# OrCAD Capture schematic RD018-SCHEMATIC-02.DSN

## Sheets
1 2: size A3
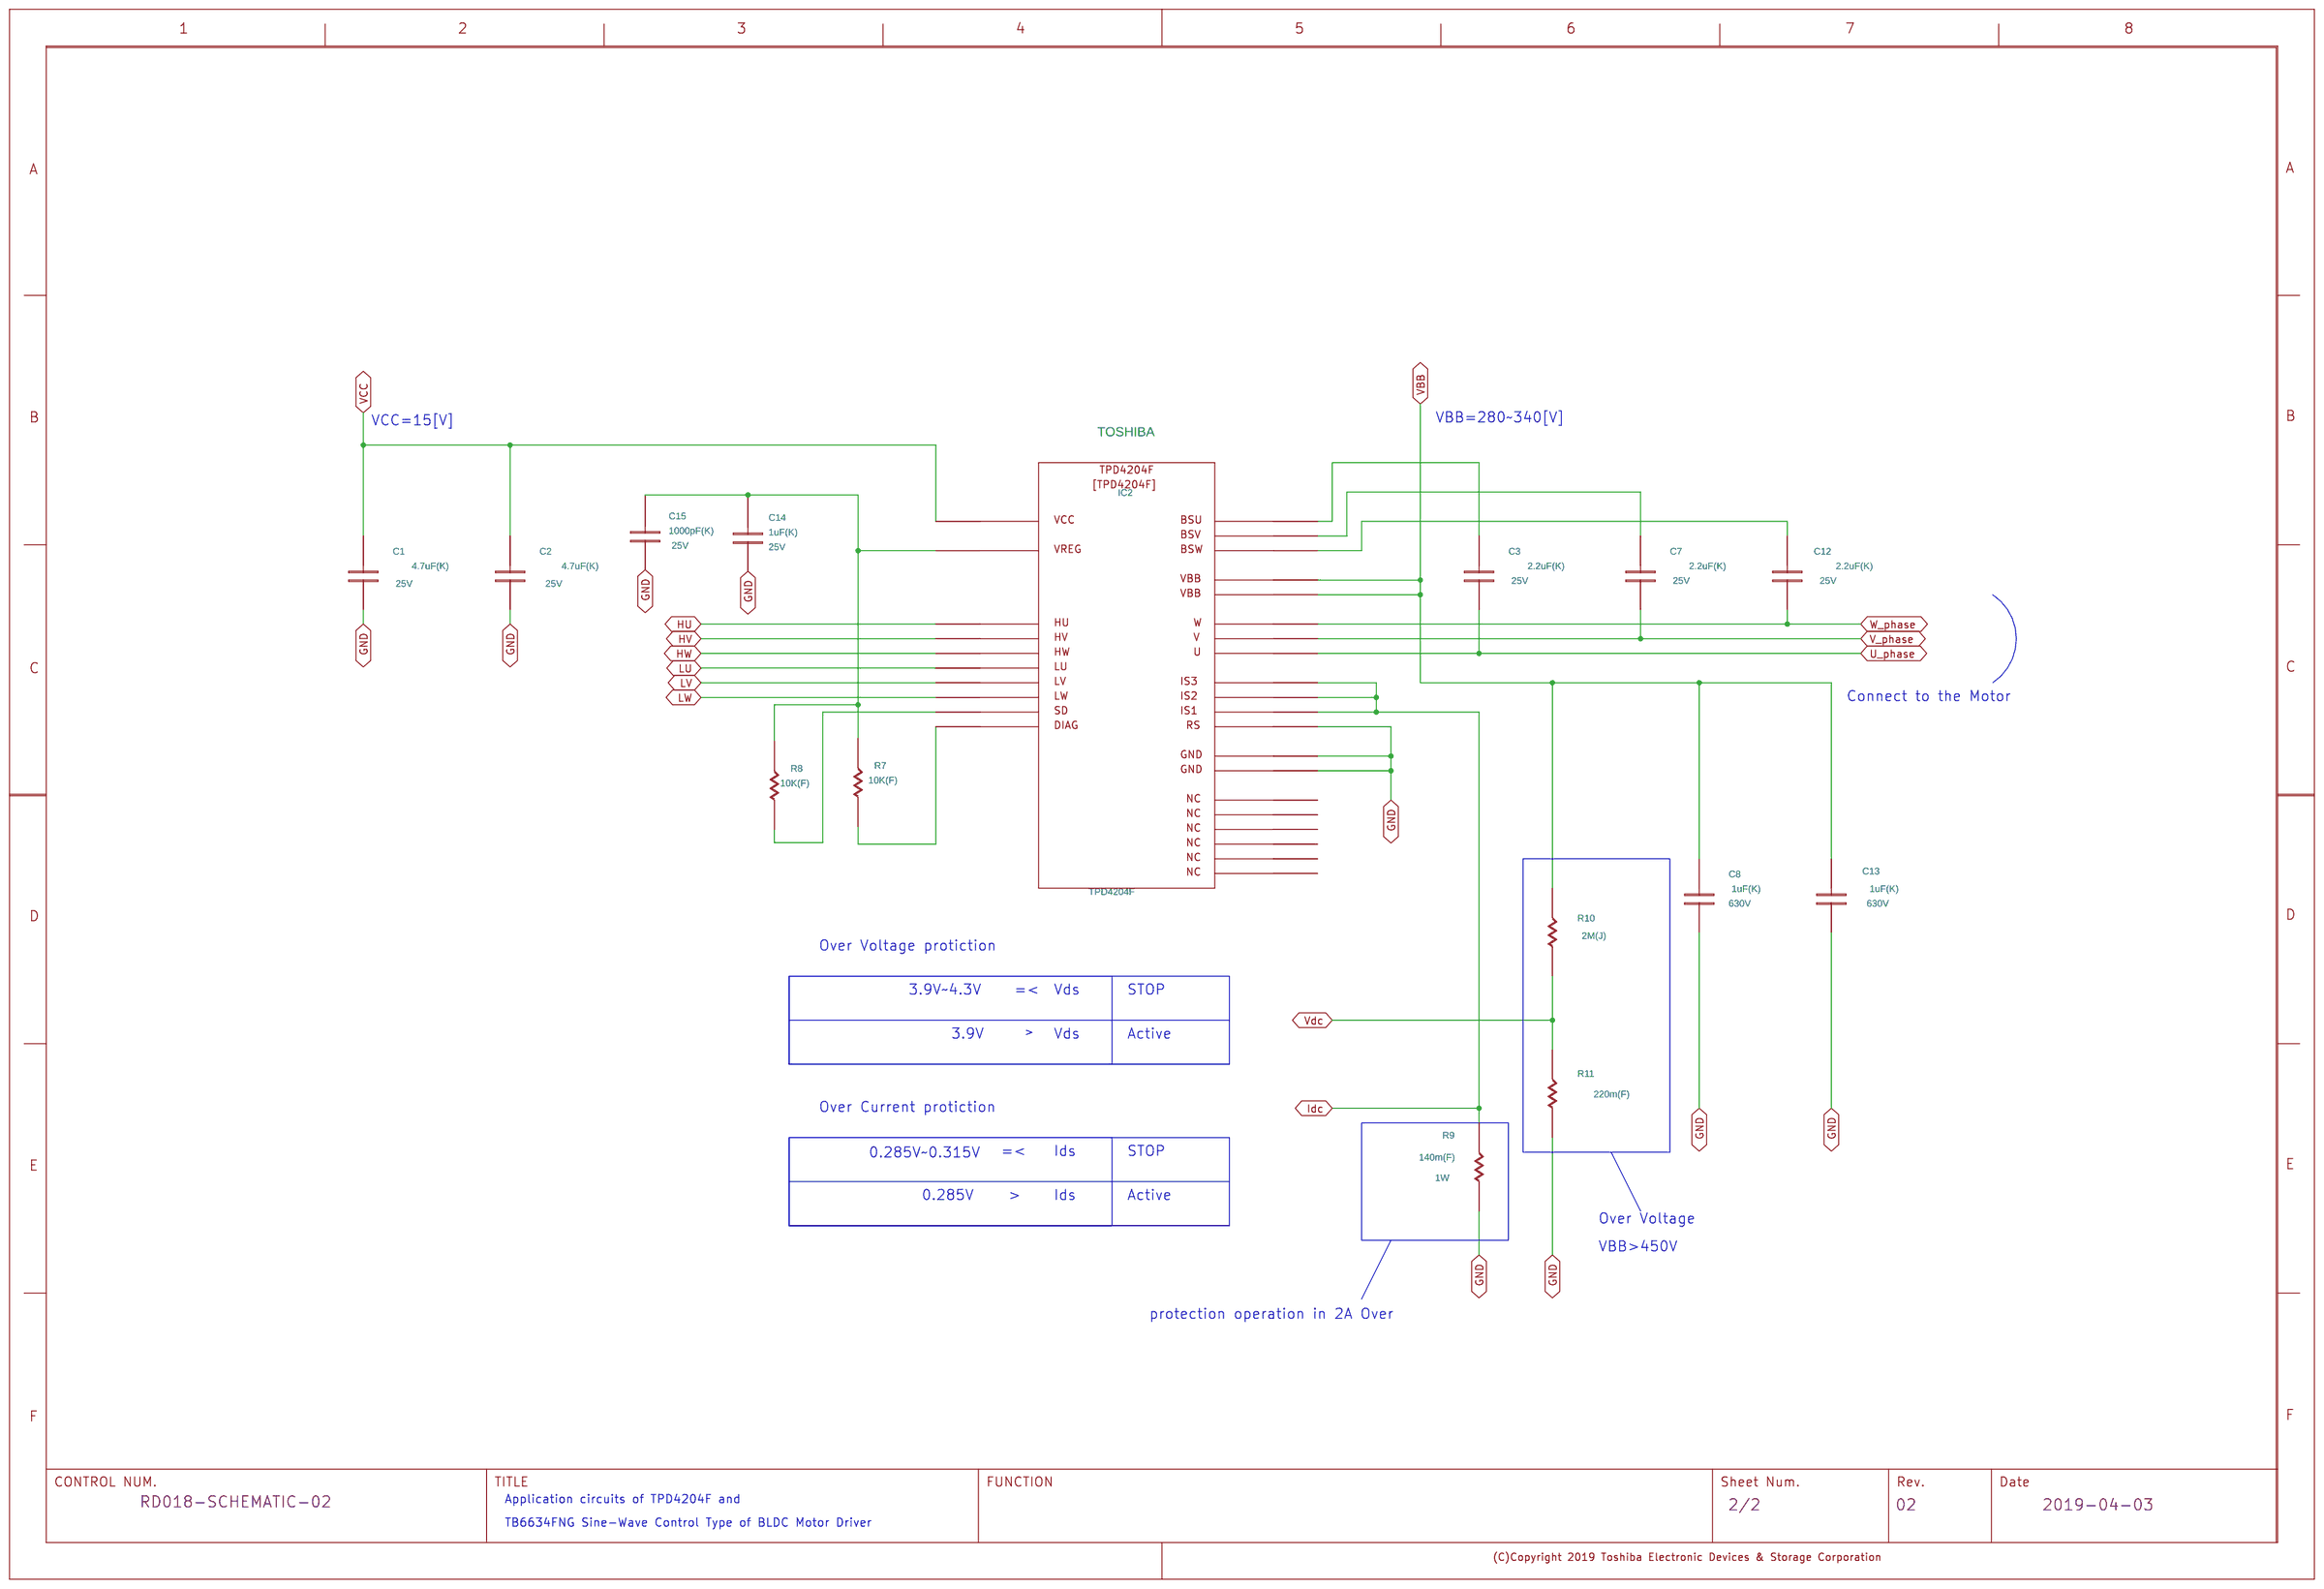
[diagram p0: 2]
2 1: size A3
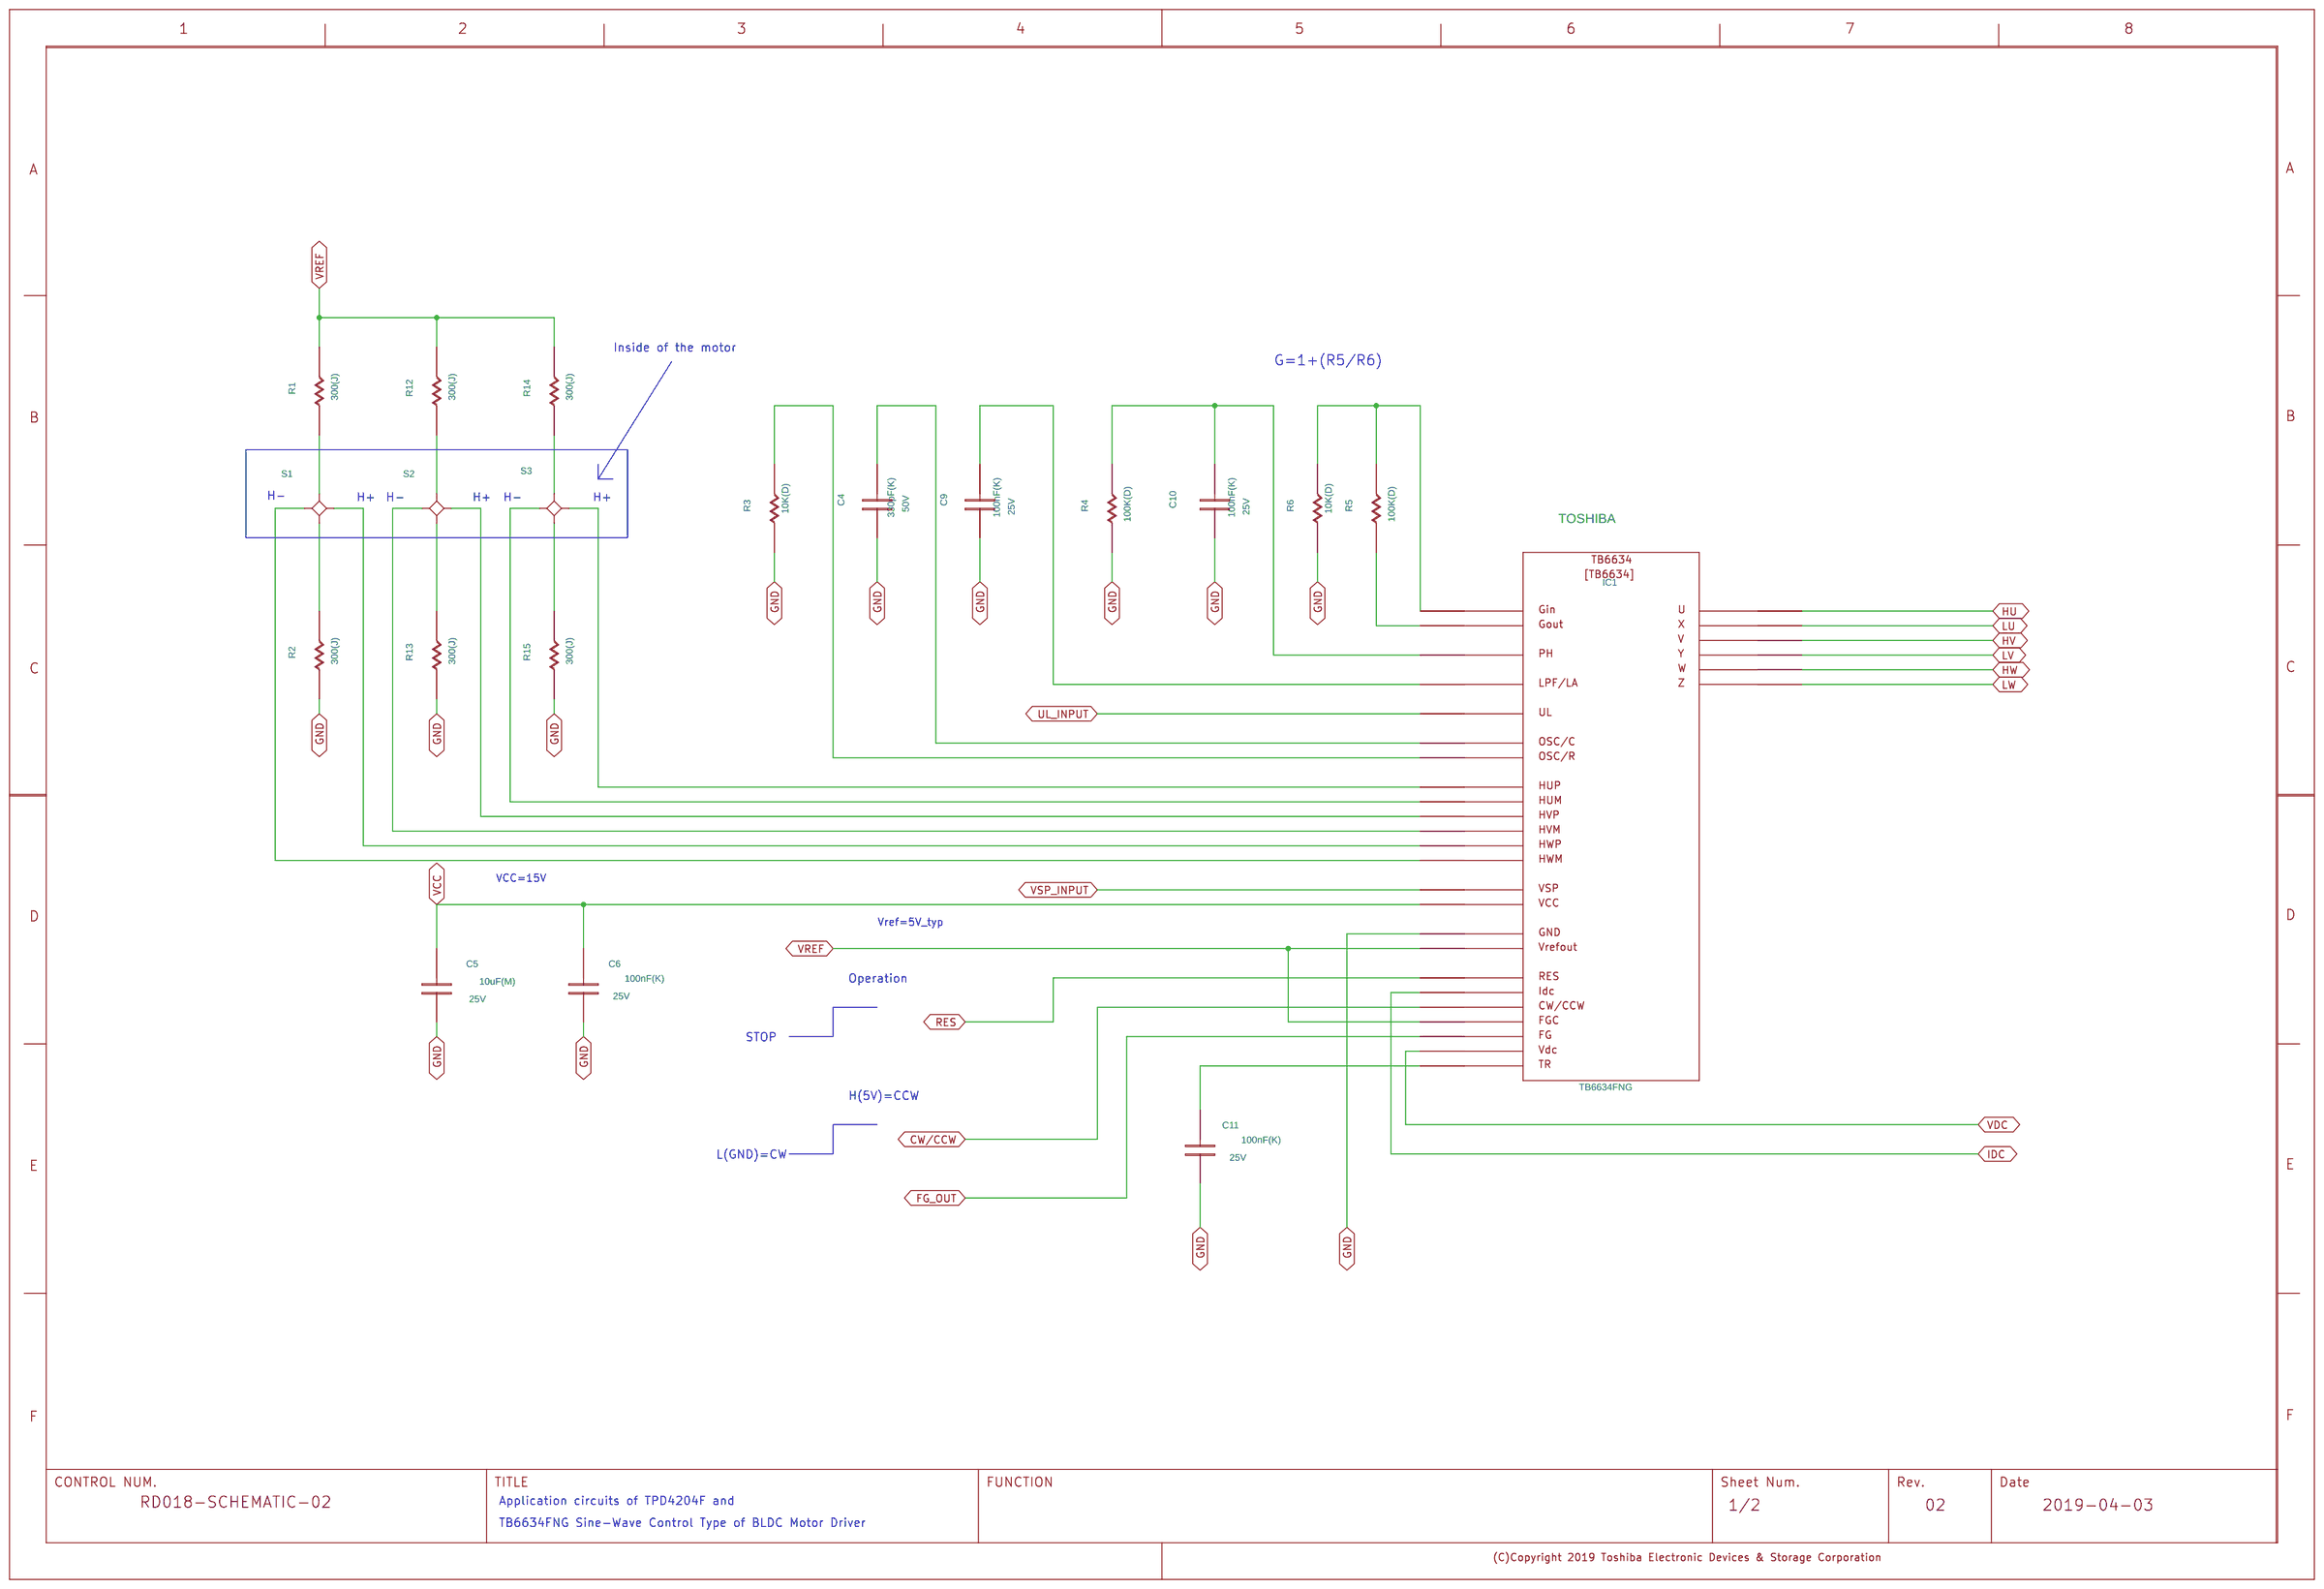
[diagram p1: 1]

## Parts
sheet 1
C4  C
C5  C
C6  C
C9  C
C10  C
C11  C
IC1  S-TB6634
R1  R
R2  R
R3  R
R4  R
R5  R
R6  R
R12  R
R13  R
R14  R
R15  R
S1  STAR4
S2  STAR4
S3  STAR4
U?#1  WAKU_DEF100
sheet 2
C1  C
C2  C
C3  C
C7  C
C8  C
C12  C
C13  C
C14  C
C15  C
IC2  S-TPD4204F
R7  R
R8  R
R9  R
R10  R
R11  R
U?#2  WAKU_DEF100

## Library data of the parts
C4 = C: COMPONENTTYPE: 4; GCOUNT: 1; MAXGCOUNT: 1; SIZECODESMD: 1608; VAL1: 330pF(K); VAL2: 50V
C5 = C: COMPONENTTYPE: 4; GCOUNT: 1; MAXGCOUNT: 1; SIZECODESMD: 2012; VAL1: 10uF(M); VAL2: 25V
C6 C9-C11 = C: COMPONENTTYPE: 4; GCOUNT: 1; MAXGCOUNT: 1; SIZECODESMD: 1608; VAL1: 100nF(K); VAL2: 25V
IC1 = S-TB6634: COMPONENTTYPE: 4; OUMEPARTTYPE: IC; SIZECODESMD: SSOP30; USERCOMPTEXT1: TB6634FNG; USERCOMPTEXT3: TOSHIBA; VAL1: TB6634FNG; VAL3: TB6634FNG
R1 R2 R12-R15 = R: COMPONENTTYPE: 4; GCOUNT: 1; MAXGCOUNT: 1; SIZECODESMD: 1608; VAL1: 300(J); VAL2: 100mW
R3 R6 = R: COMPONENTTYPE: 4; GCOUNT: 1; MAXGCOUNT: 1; SIZECODESMD: 1608; VAL1: 10K(D); VAL2: 100mW
R4 R5 = R: COMPONENTTYPE: 4; GCOUNT: 1; MAXGCOUNT: 1; SIZECODESMD: 1608; VAL1: 100K(D); VAL2: 100mW
S1-S3 = STAR4: COMPONENTTYPE: 4; OUMEPARTTYPE: IC; SIZECODESMD: 4SOP; VAL1: HW-101A; VAL3: HW-101A
U?#1 = WAKU_DEF100: COMPONENTTYPE: 2; DATE: 2019-04-03; DRAWINGNUMBER: RD018-SCHEMATIC-02; REVISION: 02; SHEETNUMBER: 1/2; TITLE: Application Circuits of TPD4204F and TB6634FNG Sine-Wave Control Type of BLDC Motor Driver; UPDATEDATE: 2018/03/19; UPDATETIME: 11:22:14; UPDATEUSER: g4302510
C1 C2 = C: COMPONENTTYPE: 4; GCOUNT: 1; MAXGCOUNT: 1; SIZECODESMD: 2012; VAL1: 4.7uF(K); VAL2: 25V; VAL3: GRM21BB31E475KA75L
C3 C7 C12 = C: COMPONENTTYPE: 4; GCOUNT: 1; MAXGCOUNT: 1; SIZECODESMD: 2012; VAL1: 2.2uF(K); VAL2: 25V; VAL3: GRM219B31E225KA75D
C8 C13 = C: COMPONENTTYPE: 4; GCOUNT: 1; MAXGCOUNT: 1; SIZECODESMD: DIP; VAL1: 1uF(K); VAL2: 630V; VAL3: ECQE6105KF
C14 = C: COMPONENTTYPE: 4; GCOUNT: 1; MAXGCOUNT: 1; SIZECODESMD: 2012; VAL1: 1uF(K); VAL2: 25V; VAL3: GRM21BB31E475KA75L
C15 = C: COMPONENTTYPE: 4; GCOUNT: 1; MAXGCOUNT: 1; SIZECODESMD: 2012; VAL1: 1000pF(K); VAL2: 25V; VAL3: GRM21BB31E475KA75L
IC2 = S-TPD4204F: COMPONENTTYPE: 4; OUMEPARTTYPE: IC; SIZECODESMD: HSSOP31; USERCOMPTEXT1: TPD4204F; USERCOMPTEXT3: TOSHIBA; VAL1: TPD4204F; VAL3: TPD4204F
R7 R8 = R: COMPONENTTYPE: 4; GCOUNT: 1; MAXGCOUNT: 1; SIZECODESMD: 1608; VAL1: 10K(F); VAL2: 100mW; VAL3: CRCW060310K0FKEA
R9 = R: COMPONENTTYPE: 4; GCOUNT: 1; MAXGCOUNT: 1; SIZECODESMD: 6332; USERCOMPTEXT1: 6332; VAL1: 140m(F); VAL2: 1W; VAL3: SL1TTER100FSMD
R10 = R: COMPONENTTYPE: 4; GCOUNT: 1; MAXGCOUNT: 1; SIZECODESMD: 6332; VAL1: 2M(J); VAL2: 1W; VAL3: TLR3ADTE2L00F
R11 = R: COMPONENTTYPE: 4; GCOUNT: 1; MAXGCOUNT: 1; SIZECODESMD: 2012; VAL1: 220m(F); VAL2: 250mW; VAL3: RL1220S-R22-F
U?#2 = WAKU_DEF100: AUTHOR: g4302510; COMPONENTTYPE: 2; DATE: 2019-04-03; DRAWINGNUMBER: RD018-SCHEMATIC-02; REVISION: 02; SAVEAREA0: -45080,-4508,463680,304612; SHEETNUMBER: 2/2; TIME: 15:28:53; TITLE: Application Circuits of TPD4204F and TB634FNG Sine-Wave Control Type of BLDC Motor Driver; UPDATEDATE: 2018/03/19; UPDATETIME: 11:22:14; UPDATEUSER: g4302510

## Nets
GND: C1.1 C2.1 C4.1 C5.1 C6.1 C8.1 C9.1 C10.1 C11.1 C13.1 C14.1 C15.1 IC1.28 IC2.8 IC2.9 IC2.16 R2.1 R3.1 R4.1 R6.1 R9.1 R11.1 R13.1 R15.1
VCC: C1.2 C2.2 C5.2 C6.2 IC1.30 IC2.5
CW/CCW: IC1.24
FG_OUT: IC1.25
HU: IC1.6 IC2.15
HV: IC1.5 IC2.14
HW: IC1.4 IC2.13
IDC: IC1.10 IC2.20 IC2.27 IC2.28 R9.2
LU: IC1.3 IC2.12
LV: IC1.2 IC2.11
LW: IC1.1 IC2.10
RES: IC1.7
U_phase: C3.1 IC2.30
UL_INPUT: IC1.15
V_phase: C7.1 IC2.26
VBB: C8.2 C13.2 IC2.23 IC2.24 R10.2
VDC: IC1.8 R10.1 R11.2
VREF: IC1.16 IC1.23 R1.2 R12.2 R14.2
VSP_INPUT: IC1.29
W_phase: C12.1 IC2.21
N00475: IC1.12 R5.1
N00481: C10.2 IC1.13 R4.2
N00531: C11.2 IC1.9
N00553: C9.2 IC1.14
N00567: C4.2 IC1.27
N00581: IC1.26 R3.2
N00595: IC1.11 R5.2 R6.2
N00625: R14.1 S3.4
N00629: R12.1 S2.4
N00637: R2.2 S1.3
N00641: R15.2 S3.3
N00649: R13.2 S2.3
N00653: R1.1 S1.4
N00661: IC1.17 S3.2
N00669: IC1.18 S3.1
N00677: IC1.19 S2.2
N00685: IC1.20 S2.1
N00693: IC1.21 S1.2
N00701: IC1.22 S1.1
N01312: C3.2 IC2.29
N01330: C7.2 IC2.25
N01348: C12.2 IC2.22
N01416: C14.2 C15.2 IC2.6 R7.2 R8.2
N05734: IC2.4 R7.1
N05763: IC2.7 R8.1

Not connected (* = marked no-connect by the designer): IC2 1 2 3 17 18 19

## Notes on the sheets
sheet 1
- VBB=280~340[V]
- VCC=15[V]
- Connect to the Motor
- Over Voltage protiction
- 3.9V~4.3V
- =<
- Vds
- STOP
- 3.9V
- >
- Vds
- Active
- Over Current protiction
- 0.285V~0.315V
- =<
- Ids
- STOP
- 0.285V
- >
- Ids
- Active
- Over Voltage
- VBB>450V
- protection operation in 2A Over
- Application circuits of TPD4204F and
- TB6634FNG Sine-Wave Control Type of BLDC Motor Driver
sheet 2
- Inside of the motor
- G=1+(R5/R6)
- H-
- H+
- H-
- H+
- H-
- H+
- VCC=15V
- Vref=5V_typ
- Operation
- STOP
- H(5V)=CCW
- L(GND)=CW
- Application circuits of TPD4204F and
- TB6634FNG Sine-Wave Control Type of BLDC Motor Driver
